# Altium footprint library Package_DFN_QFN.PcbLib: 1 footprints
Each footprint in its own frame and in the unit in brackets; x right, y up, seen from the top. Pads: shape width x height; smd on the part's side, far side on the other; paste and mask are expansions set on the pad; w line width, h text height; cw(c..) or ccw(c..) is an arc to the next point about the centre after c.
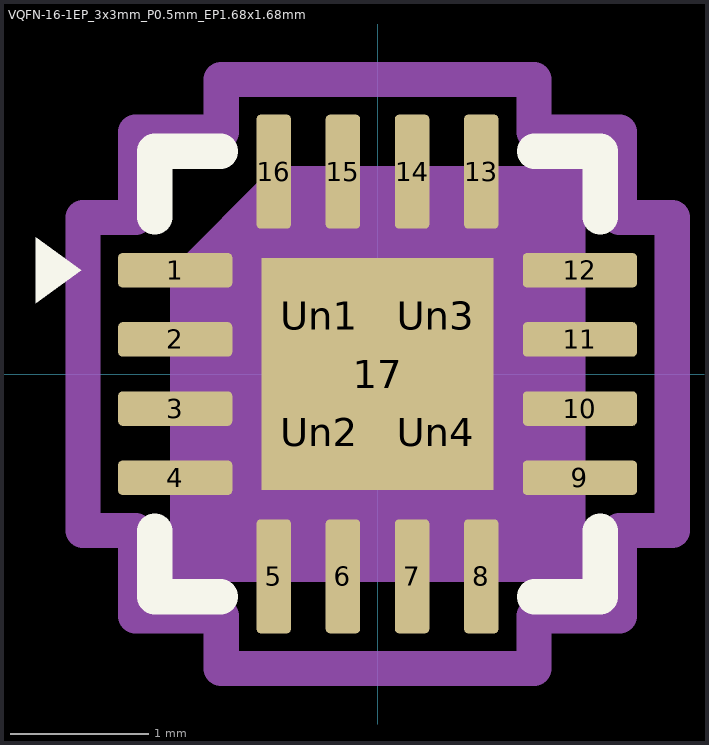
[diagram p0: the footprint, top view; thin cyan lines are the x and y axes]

## VQFN-16-1EP_3x3mm_P0.5mm_EP1.68x1.68mm [mm]
pads (21):
  rrect25% 0.825x0.25 smd: 1(-1.462,0.75) 2(-1.462,0.25) 3(-1.462,-0.25) 4(-1.462,-0.75) 9(1.462,-0.75) 10(1.462,-0.25) 11(1.462,0.25) 12(1.462,0.75)
  rrect25% 0.25x0.825 smd: 5(-0.75,-1.462) 6(-0.25,-1.462) 7(0.25,-1.462) 8(0.75,-1.462) 13(0.75,1.462) 14(0.25,1.462) 15(-0.25,1.462) 16(-0.75,1.462)
  rect 1.68x1.68 smd: 17(0,0)
  rrect25% 0.68x0.68 on Top Paste: Un1(-0.42,0.42) Un2(-0.42,-0.42) Un3(0.42,0.42) Un4(0.42,-0.42)
F.SilkS:
  region: -2.14,0.75 -2.47,0.51 -2.47,0.99
  lines w0.254: -1.61,-1.135 -1.61,-1.61 -1.135,-1.61 ; -1.61,1.135 -1.61,1.61 -1.135,1.61 ; 1.135,-1.61 1.61,-1.61 1.61,-1.135 ; 1.135,1.61 1.61,1.61 1.61,1.135
F.CrtYd:
  lines w0.254: -2.13,-1.13 -2.13,1.13 -1.75,1.13 -1.75,1.75 -1.13,1.75 -1.13,2.13 1.13,2.13 1.13,1.75 1.75,1.75 1.75,1.13 2.13,1.13 2.13,-1.13 1.75,-1.13 1.75,-1.75 1.13,-1.75 1.13,-2.13 -1.13,-2.13 -1.13,-1.75 -1.75,-1.75 -1.75,-1.13 -2.13,-1.13
F.Fab:
  region: 1.5,-1.5 -1.5,-1.5 -1.5,0.75 -0.75,1.5 1.5,1.5
  text "'.Designator'" at -3.033,-0.628 h0.75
